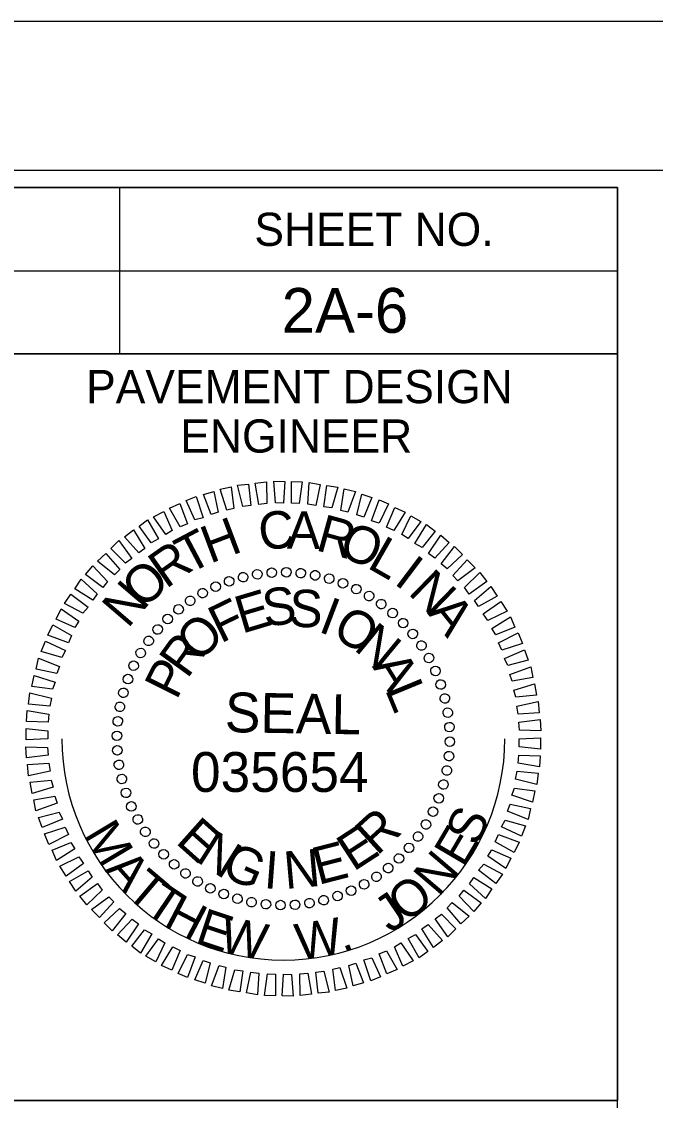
# Model space of a CAD drawing. Extents: x 957297 to 961629, y 830661 to 840840.
# Drawn here: x 960288 to 960383.5, y 834216.4 to 834378.9 of the extents above; entities that cross this region are included whole.
import ezdxf

# ---------------------------------------------------------------- set-up
doc = ezdxf.new("R2010")
doc.units = 0
for name, color, linetype in [('Scratch_Level_0', 7, 'Continuous'), ('Sheet Data Field CELL', 7, 'Continuous'), ('Sheet Plot Border Inside CELL', 7, 'Continuous'), ('Sheet Plot Border Outside CELL', 7, 'Continuous'), ('Sheet Professional Seal CELL', 7, 'Continuous'), ('Sheet Profile Grid Minor CELL', 7, 'Continuous'), ('Sheet Sticker Exception Certification CELL', 7, 'Continuous'), ('Sheet Typical CELL', 7, 'Continuous')]:
    doc.layers.add(name, color=color, linetype=linetype)

msp = doc.modelspace()

# ---------------------------------------------------------------- linework, layer by layer
at = {"layer": 'Scratch_Level_0'}
msp.add_arc((960327.47, 834270.85), 33.36, 180, 360, dxfattribs=at)
at = {"layer": 'Sheet Plot Border Inside CELL'}
msp.add_lwpolyline([(960390.3, 834356.46), (958723.8, 834356.46), (958723.8, 833301.36), (960390.3, 833301.36)], close=True, dxfattribs=at)
at = {"layer": 'Sheet Plot Border Outside CELL'}
msp.add_lwpolyline([(960394.8, 834378.91), (958710.8, 834378.91), (958710.8, 833278.91), (960394.8, 833278.91)], close=True, dxfattribs=at)
at = {"layer": 'Sheet Professional Seal CELL'}
for p, q in [((960323.57, 834295.6), (960323.57, 834295.6)), ((960325.72, 834295.9), (960325.72, 834295.9)), ((960327.92, 834295.95), (960327.92, 834295.95)), ((960330.12, 834295.8), (960330.12, 834295.8)), ((960319.27, 834294.6), (960319.27, 834294.6)), ((960321.37, 834295.2), (960321.37, 834295.2)), ((960332.27, 834295.45), (960332.27, 834295.45)), ((960334.37, 834295), (960334.37, 834295)), ((960336.47, 834294.3), (960336.47, 834294.3)), ((960315.32, 834292.8), (960315.32, 834292.8)), ((960317.27, 834293.8), (960317.27, 834293.8)), ((960338.47, 834293.4), (960338.47, 834293.4)), ((960340.42, 834292.4), (960340.42, 834292.4)), ((960313.42, 834291.65), (960313.42, 834291.65)), ((960342.22, 834291.15), (960342.22, 834291.15)), ((960311.67, 834290.4), (960311.67, 834290.4)), ((960343.97, 834289.8), (960343.97, 834289.8)), ((960310.02, 834288.9), (960310.02, 834288.9)), ((960345.52, 834288.3), (960345.52, 834288.3)), ((960308.52, 834287.35), (960308.52, 834287.35)), ((960347.02, 834286.65), (960347.02, 834286.65)), ((960307.17, 834285.6), (960307.17, 834285.6)), ((960348.27, 834284.9), (960348.27, 834284.9)), ((960305.92, 834283.8), (960305.92, 834283.8)), ((960349.42, 834283), (960349.42, 834283)), ((960304.92, 834281.85), (960304.92, 834281.85)), ((960350.42, 834281.05), (960350.42, 834281.05)), ((960304.02, 834279.85), (960304.02, 834279.85)), ((960303.32, 834277.75), (960303.32, 834277.75)), ((960351.22, 834279.05), (960351.22, 834279.05)), ((960351.82, 834276.95), (960351.82, 834276.95)), ((960302.87, 834275.65), (960302.87, 834275.65)), ((960352.22, 834274.75), (960352.22, 834274.75)), ((960302.52, 834273.5), (960302.52, 834273.5)), ((960302.37, 834271.3), (960302.37, 834271.3)), ((960352.52, 834272.6), (960352.52, 834272.6)), ((960327.47, 834270.85), (960327.47, 834270.85)), ((960352.57, 834270.4), (960352.57, 834270.4)), ((960302.42, 834269.1), (960302.42, 834269.1)), ((960352.42, 834268.2), (960352.42, 834268.2)), ((960302.72, 834266.95), (960302.72, 834266.95)), ((960303.12, 834264.75), (960303.12, 834264.75)), ((960352.07, 834266.05), (960352.07, 834266.05)), ((960351.62, 834263.95), (960351.62, 834263.95)), ((960303.72, 834262.65), (960303.72, 834262.65)), ((960350.92, 834261.85), (960350.92, 834261.85)), ((960304.52, 834260.65), (960304.52, 834260.65)), ((960350.02, 834259.85), (960350.02, 834259.85)), ((960305.52, 834258.7), (960305.52, 834258.7)), ((960306.67, 834256.8), (960306.67, 834256.8)), ((960349.02, 834257.9), (960349.02, 834257.9)), ((960307.92, 834255.05), (960307.92, 834255.05)), ((960347.77, 834256.1), (960347.77, 834256.1)), ((960309.42, 834253.4), (960309.42, 834253.4)), ((960346.42, 834254.35), (960346.42, 834254.35)), ((960310.97, 834251.9), (960310.97, 834251.9)), ((960344.92, 834252.8), (960344.92, 834252.8)), ((960312.72, 834250.55), (960312.72, 834250.55)), ((960343.27, 834251.3), (960343.27, 834251.3)), ((960314.52, 834249.3), (960314.52, 834249.3)), ((960339.62, 834248.9), (960339.62, 834248.9)), ((960341.52, 834250.05), (960341.52, 834250.05)), ((960316.47, 834248.3), (960316.47, 834248.3)), ((960318.47, 834247.4), (960318.47, 834247.4)), ((960335.67, 834247.1), (960335.67, 834247.1)), ((960337.67, 834247.9), (960337.67, 834247.9)), ((960320.57, 834246.7), (960320.57, 834246.7)), ((960322.67, 834246.25), (960322.67, 834246.25)), ((960324.82, 834245.9), (960324.82, 834245.9)), ((960327.02, 834245.75), (960327.02, 834245.75)), ((960329.22, 834245.8), (960329.22, 834245.8)), ((960331.37, 834246.1), (960331.37, 834246.1)), ((960333.57, 834246.5), (960333.57, 834246.5))]:
    msp.add_line(p, q, dxfattribs=at)
for points in [[(960318.97, 834305.3), (960317.92, 834308.45), (960319.62, 834308.8), (960320.02, 834305.55)], [(960321.37, 834305.85), (960320.57, 834309.05), (960322.22, 834309.2), (960322.57, 834306)], [(960323.77, 834306.15), (960323.22, 834309.35), (960324.92, 834309.55), (960324.97, 834306.3)], [(960326.27, 834306.4), (960326.02, 834309.65), (960327.67, 834309.6), (960327.47, 834306.35)], [(960328.67, 834306.35), (960328.67, 834309.6), (960330.32, 834309.55), (960329.87, 834306.3)], [(960331.17, 834306.2), (960331.37, 834309.45), (960333.02, 834309.15), (960332.37, 834306)], [(960333.57, 834305.8), (960334.02, 834309), (960335.67, 834308.75), (960334.77, 834305.65)], [(960314.12, 834303.85), (960312.82, 834306.75), (960314.32, 834307.35), (960315.37, 834304.15)], [(960316.57, 834304.65), (960315.42, 834307.65), (960316.97, 834308.1), (960317.62, 834305)], [(960336.12, 834305.25), (960336.62, 834308.5), (960338.32, 834308.1), (960337.17, 834305)], [(960338.52, 834304.6), (960339.27, 834307.7), (960340.82, 834307.2), (960339.57, 834304.25)], [(960311.92, 834302.8), (960310.32, 834305.6), (960311.87, 834306.3), (960313.02, 834303.25)], [(960340.77, 834303.7), (960341.92, 834306.85), (960343.32, 834306.25), (960341.92, 834303.35)], [(960343.02, 834302.75), (960344.27, 834305.7), (960345.82, 834305), (960344.12, 834302.2)], [(960307.57, 834300.35), (960305.72, 834302.9), (960307.02, 834303.85), (960308.67, 834300.95)], [(960309.77, 834301.6), (960307.92, 834304.3), (960309.47, 834305.1), (960310.72, 834302.2)], [(960345.32, 834301.6), (960346.67, 834304.45), (960348.17, 834303.6), (960346.27, 834301)], [(960305.67, 834298.85), (960303.52, 834301.25), (960304.87, 834302.3), (960306.62, 834299.5)], [(960347.27, 834300.25), (960349.02, 834303.15), (960350.32, 834302.1), (960348.37, 834299.65)], [(960303.67, 834297.3), (960301.47, 834299.5), (960302.67, 834300.7), (960304.62, 834298)], [(960349.32, 834298.75), (960351.17, 834301.5), (960352.47, 834300.4), (960350.27, 834298.05)], [(960351.22, 834297.2), (960353.27, 834299.8), (960354.47, 834298.6), (960352.17, 834296.45)], [(960302.02, 834295.55), (960299.47, 834297.6), (960300.72, 834298.75), (960302.82, 834296.35)], [(960353.02, 834295.45), (960355.17, 834297.8), (960356.37, 834296.6), (960353.77, 834294.65)], [(960300.27, 834293.65), (960297.67, 834295.6), (960298.77, 834296.9), (960300.97, 834294.55)], [(960354.77, 834293.65), (960357.07, 834295.9), (960358.12, 834294.55), (960355.47, 834292.65)], [(960298.77, 834291.75), (960296.07, 834293.45), (960297.02, 834294.9), (960299.42, 834292.7)], [(960297.27, 834289.75), (960294.47, 834291.25), (960295.47, 834292.65), (960298.07, 834290.65)], [(960356.27, 834291.7), (960358.72, 834293.8), (960359.67, 834292.35), (960356.87, 834290.75)], [(960357.57, 834289.65), (960360.22, 834291.55), (960361.17, 834290.05), (960358.27, 834288.65)], [(960296.07, 834287.6), (960293.22, 834288.85), (960293.97, 834290.4), (960296.67, 834288.55)], [(960358.87, 834287.45), (960361.67, 834289.2), (960362.32, 834287.65), (960359.47, 834286.5)], [(960295.07, 834285.3), (960291.97, 834286.45), (960292.72, 834288), (960295.57, 834286.4)], [(960359.87, 834285.3), (960362.82, 834286.8), (960363.47, 834285.2), (960360.37, 834284.2)], [(960294.07, 834283.1), (960290.97, 834284), (960291.62, 834285.55), (960294.62, 834284.15)], [(960360.77, 834282.95), (960363.82, 834284.25), (960364.37, 834282.7), (960361.27, 834281.9)], [(960293.32, 834280.7), (960290.22, 834281.35), (960290.57, 834283), (960293.72, 834281.75)], [(960361.57, 834280.55), (960364.77, 834281.7), (960365.07, 834280.05), (960361.92, 834279.5)], [(960292.67, 834278.3), (960289.57, 834278.7), (960289.92, 834280.4), (960293.07, 834279.35)], [(960292.27, 834275.75), (960289.07, 834276.05), (960289.27, 834277.75), (960292.52, 834276.95)], [(960362.17, 834278.15), (960365.32, 834279.1), (960365.62, 834277.4), (960362.47, 834277.1)], [(960362.62, 834275.75), (960365.87, 834276.45), (960366.02, 834274.75), (960362.82, 834274.55)], [(960292.02, 834273.35), (960288.77, 834273.45), (960288.87, 834275.1), (960292.12, 834274.55)], [(960362.92, 834273.35), (960366.17, 834273.75), (960366.27, 834272.05), (960363.02, 834272.15)], [(960291.97, 834270.85), (960288.72, 834270.7), (960288.72, 834272.4), (960291.97, 834272.05)], [(960292.02, 834268.35), (960288.77, 834267.95), (960288.67, 834269.65), (960291.92, 834269.55)], [(960362.97, 834270.85), (960366.22, 834271), (960366.22, 834269.3), (960362.97, 834269.65)], [(960362.92, 834268.35), (960366.17, 834268.25), (960366.07, 834266.6), (960362.82, 834267.15)], [(960292.32, 834265.95), (960289.07, 834265.25), (960288.92, 834266.95), (960292.12, 834267.15)], [(960362.67, 834265.95), (960365.87, 834265.65), (960365.67, 834263.95), (960362.42, 834264.75)], [(960292.77, 834263.55), (960289.62, 834262.6), (960289.32, 834264.3), (960292.47, 834264.6)], [(960362.27, 834263.4), (960365.37, 834263), (960365.02, 834261.3), (960361.87, 834262.35)], [(960293.37, 834261.15), (960290.17, 834260), (960289.87, 834261.65), (960293.02, 834262.2)], [(960361.62, 834261), (960364.72, 834260.35), (960364.37, 834258.7), (960361.22, 834259.95)], [(960294.17, 834258.75), (960291.12, 834257.45), (960290.57, 834259), (960293.67, 834259.8)], [(960360.87, 834258.6), (960363.97, 834257.7), (960363.32, 834256.15), (960360.32, 834257.55)], [(960295.07, 834256.4), (960292.12, 834254.9), (960291.47, 834256.5), (960294.57, 834257.5)], [(960296.07, 834254.25), (960293.27, 834252.5), (960292.62, 834254.05), (960295.47, 834255.2)], [(960359.87, 834256.4), (960362.97, 834255.25), (960362.22, 834253.7), (960359.37, 834255.3)], [(960358.87, 834254.1), (960361.72, 834252.85), (960360.97, 834251.3), (960358.27, 834253.15)], [(960297.37, 834252.05), (960294.72, 834250.15), (960293.77, 834251.65), (960296.67, 834253.05)], [(960357.67, 834251.95), (960360.47, 834250.45), (960359.47, 834249.05), (960356.87, 834251.05)], [(960298.67, 834250), (960296.22, 834247.9), (960295.27, 834249.35), (960298.07, 834250.95)], [(960300.17, 834248.05), (960297.87, 834245.8), (960296.82, 834247.15), (960299.47, 834249.05)], [(960356.17, 834249.95), (960358.87, 834248.25), (960357.92, 834246.8), (960355.52, 834249)], [(960301.92, 834246.25), (960299.77, 834243.9), (960298.57, 834245.1), (960301.17, 834247.05)], [(960354.67, 834248.05), (960357.27, 834246.1), (960356.17, 834244.8), (960353.97, 834247.15)], [(960303.72, 834244.5), (960301.67, 834241.9), (960300.47, 834243.1), (960302.77, 834245.25)], [(960352.92, 834246.15), (960355.47, 834244.1), (960354.22, 834242.95), (960352.12, 834245.35)], [(960305.62, 834242.95), (960303.77, 834240.2), (960302.47, 834241.3), (960304.67, 834243.65)], [(960351.27, 834244.4), (960353.47, 834242.2), (960352.27, 834241), (960350.32, 834243.7)], [(960307.67, 834241.45), (960305.92, 834238.55), (960304.62, 834239.6), (960306.57, 834242.05)], [(960349.27, 834242.85), (960351.42, 834240.45), (960350.07, 834239.4), (960348.32, 834242.2)], [(960309.62, 834240.1), (960308.27, 834237.25), (960306.77, 834238.1), (960308.67, 834240.7)], [(960347.37, 834241.35), (960349.22, 834238.8), (960347.92, 834237.85), (960346.27, 834240.75)], [(960311.92, 834238.95), (960310.67, 834236), (960309.12, 834236.7), (960310.82, 834239.5)], [(960343.02, 834238.9), (960344.62, 834236.1), (960343.07, 834235.4), (960341.92, 834238.45)], [(960345.17, 834240.1), (960347.02, 834237.4), (960345.47, 834236.6), (960344.22, 834239.5)], [(960314.17, 834238), (960313.02, 834234.85), (960311.62, 834235.45), (960313.02, 834238.35)], [(960316.42, 834237.1), (960315.67, 834234), (960314.12, 834234.5), (960315.37, 834237.45)], [(960338.37, 834237.05), (960339.52, 834234.05), (960337.97, 834233.6), (960337.32, 834236.7)], [(960340.82, 834237.85), (960342.12, 834234.95), (960340.62, 834234.35), (960339.57, 834237.55)], [(960318.82, 834236.45), (960318.32, 834233.2), (960316.62, 834233.6), (960317.77, 834236.7)], [(960321.37, 834235.9), (960320.92, 834232.7), (960319.27, 834232.95), (960320.17, 834236.05)], [(960323.77, 834235.5), (960323.57, 834232.25), (960321.92, 834232.55), (960322.57, 834235.7)], [(960331.17, 834235.55), (960331.72, 834232.35), (960330.02, 834232.15), (960329.97, 834235.4)], [(960333.57, 834235.85), (960334.37, 834232.65), (960332.72, 834232.5), (960332.37, 834235.7)], [(960335.97, 834236.4), (960337.02, 834233.25), (960335.32, 834232.9), (960334.92, 834236.15)], [(960326.27, 834235.35), (960326.27, 834232.1), (960324.62, 834232.15), (960325.07, 834235.4)], [(960328.67, 834235.3), (960328.92, 834232.05), (960327.27, 834232.1), (960327.47, 834235.35)]]:
    msp.add_lwpolyline(points, close=True, dxfattribs=at)
for centre, major_axis in [((960321.4, 834295.19), (-0.174, 0.699)), ((960323.54, 834295.62), (-0.113, 0.711)), ((960325.72, 834295.87), (-0.05, 0.718)), ((960327.9, 834295.93), (0.013, 0.72)), ((960330.09, 834295.79), (0.075, 0.716)), ((960332.25, 834295.47), (0.137, 0.707)), ((960334.38, 834294.96), (0.198, 0.692)), ((960317.27, 834293.76), (-0.293, 0.658)), ((960319.3, 834294.57), (-0.234, 0.681)), ((960336.45, 834294.27), (0.258, 0.672)), ((960338.46, 834293.39), (0.316, 0.647)), ((960313.44, 834291.64), (-0.403, 0.597)), ((960315.31, 834292.79), (-0.349, 0.63)), ((960340.38, 834292.35), (0.371, 0.617)), ((960311.68, 834290.34), (-0.453, 0.56)), ((960342.21, 834291.14), (0.423, 0.582)), ((960310.04, 834288.89), (-0.5, 0.518)), ((960343.92, 834289.78), (0.472, 0.543)), ((960345.51, 834288.27), (0.518, 0.5)), ((960308.54, 834287.31), (-0.543, 0.472)), ((960346.96, 834286.64), (0.56, 0.453)), ((960307.18, 834285.59), (-0.582, 0.423)), ((960305.97, 834283.77), (-0.617, 0.371)), ((960348.26, 834284.88), (0.597, 0.403)), ((960304.92, 834281.85), (-0.647, 0.316)), ((960349.4, 834283.01), (0.63, 0.349)), ((960350.38, 834281.05), (0.658, 0.293)), ((960304.05, 834279.84), (-0.672, 0.258)), ((960351.18, 834279.02), (0.681, 0.234)), ((960303.36, 834277.77), (-0.692, 0.198)), ((960351.8, 834276.92), (0.699, 0.174)), ((960302.85, 834275.64), (-0.707, 0.137)), ((960352.24, 834274.78), (0.711, 0.113)), ((960302.52, 834273.47), (-0.716, 0.075)), ((960352.49, 834272.6), (0.718, 0.05)), ((960302.39, 834271.29), (-0.72, 0.013)), ((960302.45, 834269.1), (-0.718, -0.05)), ((960352.54, 834270.41), (0.72, -0.013)), ((960352.41, 834268.23), (0.716, -0.075)), ((960302.69, 834266.93), (-0.711, -0.113)), ((960352.09, 834266.07), (0.707, -0.137)), ((960303.13, 834264.78), (-0.699, -0.174)), ((960351.57, 834263.94), (0.692, -0.198)), ((960303.75, 834262.69), (-0.681, -0.234)), ((960304.55, 834260.65), (-0.658, -0.293)), ((960350.88, 834261.86), (0.672, -0.258)), ((960350.01, 834259.86), (0.647, -0.316)), ((960305.53, 834258.69), (-0.63, -0.349)), ((960348.96, 834257.93), (0.617, -0.371)), ((960306.67, 834256.83), (-0.597, -0.403)), ((960347.76, 834256.11), (0.582, -0.423)), ((960307.98, 834255.07), (-0.56, -0.453)), ((960346.39, 834254.4), (0.543, -0.472)), ((960309.43, 834253.43), (-0.518, -0.5)), ((960344.89, 834252.81), (0.5, -0.518)), ((960311.01, 834251.92), (-0.472, -0.543)), ((960343.25, 834251.36), (0.453, -0.56)), ((960312.72, 834250.56), (-0.423, -0.582)), ((960314.55, 834249.35), (-0.371, -0.617)), ((960341.49, 834250.06), (0.403, -0.597)), ((960316.47, 834248.31), (-0.316, -0.647)), ((960337.67, 834247.94), (0.293, -0.658)), ((960339.63, 834248.92), (0.349, -0.63)), ((960318.48, 834247.44), (-0.258, -0.672)), ((960320.55, 834246.74), (-0.198, -0.692)), ((960322.68, 834246.23), (-0.137, -0.707)), ((960331.39, 834246.08), (0.113, -0.711)), ((960333.53, 834246.52), (0.174, -0.699)), ((960335.63, 834247.14), (0.234, -0.681)), ((960324.84, 834245.91), (-0.075, -0.716)), ((960327.03, 834245.78), (-0.013, -0.72)), ((960329.22, 834245.83), (0.05, -0.718))]:
    msp.add_ellipse(centre, major_axis=major_axis, ratio=0.999708, dxfattribs=at)
at = {"layer": 'Sheet Sticker Exception Certification CELL'}
msp.add_line((960177.75, 834216.36), (960377.79, 834216.36), dxfattribs=at)
at = {"layer": 'Sheet Typical CELL'}
for p, q in [((960302.8, 834353.86), (960302.8, 834328.86)), ((960177.75, 834341.36), (960377.8, 834341.36))]:
    msp.add_line(p, q, dxfattribs=at)
for points in [[(960377.8, 834353.91), (958877.8, 834353.91), (958877.8, 833303.91), (960377.8, 833303.91)], [(960177.75, 834353.91), (960377.8, 834353.91), (960377.8, 834328.86), (960177.75, 834328.86)], [(960277.8, 834328.86), (960377.8, 834328.86), (960377.8, 834216.36), (960277.8, 834216.36)]]:
    msp.add_lwpolyline(points, close=True, dxfattribs=at)

# ---------------------------------------------------------------- texts
at = {"layer": 'Sheet Data Field CELL'}
msp.add_text('2A-6', height=6.75, dxfattribs=at).set_placement((960327.21, 834332.01))
at = {"layer": 'Sheet Professional Seal CELL'}
for s, height, rotation, p in [('H', 5.64, 20.6195, (960316.42, 834297.2)), ('C', 5.64, 6.2199, (960324.02, 834299.2)), ('A', 5.64, 359.0203, (960327.97, 834299.5)), ('R', 5.64, 344.6211, (960332.17, 834299.3)), ('T', 5.64, 27.8198, (960313.17, 834295.55)), ('O', 5.64, 337.4212, (960335.52, 834298.55)), ('L', 5.64, 330.2209, (960339.92, 834296.7)), ('R', 5.64, 35.0205, (960309.77, 834293.35)), ('O', 5.64, 42.2217, (960306.32, 834290.25)), ('I', 5.64, 323.0201, (960343.97, 834294.3)), ('N', 5.64, 315.8189, (960346.12, 834292.75)), ('N', 5.64, 49.4235, (960304.02, 834287.35)), ('E', 5.64, 16.6111, (960321.22, 834286.65)), ('S', 5.64, 7.2556, (960324.67, 834287.7)), ('S', 5.64, 357.9004, (960328.27, 834287.75)), ('F', 5.64, 25.967, (960318.02, 834285.15)), ('I', 5.64, 339.1896, (960332.57, 834287.05)), ('A', 5.64, 308.6172, (960349.07, 834289.8)), ('O', 5.64, 44.6812, (960314.72, 834282.2)), ('O', 5.64, 329.8335, (960334.57, 834286.35)), ('N', 5.64, 320.4766, (960337.92, 834284.35)), ('R', 5.64, 54.0397, (960312.97, 834279.75)), ('P', 5.64, 63.3989, (960311.37, 834276.55)), ('A', 5.64, 301.7603, (960340.77, 834281.75)), ('L', 5.64, 292.4008, (960342.72, 834278.3)), ('SEAL', 5.998, 359, (960318.62, 834271.85)), ('R', 5.64, 42.4814, (960341.57, 834253.1)), ('E', 5.64, 318.2769, (960311.07, 834255.2)), ('N', 5.64, 327.634, (960314.07, 834252.5)), ('E', 5.64, 33.1241, (960338.02, 834250.75)), ('E', 5.64, 14.4118, (960332.72, 834248.8)), ('G', 5.64, 336.9902, (960317.87, 834250.25)), ('I', 5.64, 355.7012, (960324.42, 834248.35)), ('N', 5.64, 5.0564, (960327.77, 834248.2))]:
    msp.add_text(s, height=height, rotation=rotation, dxfattribs=at).set_placement(p)
at = {"layer": 'Sheet Profile Grid Minor CELL'}
msp.add_text('035654', height=5.998, dxfattribs=at).set_placement((960313.55, 834262.84))
for s, rotation, p in [('S', 66.1201, (960356.72, 834254.5)), ('M', 300.9117, (960297.24, 834256.38)), ('E', 59.5371, (960354.65, 834251.26)), ('N', 49.6054, (960350.86, 834246.86)), ('A', 311.5876, (960300.45, 834251.03)), ('T', 319.7734, (960303.55, 834247.39)), ('T', 326.0702, (960306.26, 834244.9)), ('O', 38.9008, (960346, 834242.94)), ('H', 332.3669, (960309.24, 834242.74)), ('J', 34.0323, (960343.56, 834241.46)), ('E', 341.6117, (960313.99, 834240.17)), ('W', 348.1947, (960317.6, 834238.83)), ('W', 9.2459, (960329.76, 834237.42)), ('.', 20.852, (960336.44, 834238.57))]:
    msp.add_text(s, height=5.5, rotation=rotation, dxfattribs=at).set_placement(p)
at = {"layer": 'Sheet Typical CELL'}
for s, height, p in [('SHEET NO.', 5, (960323.1, 834345.11)), ('PAVEMENT DESIGN', 5.0001, (960297.75, 834321.41)), ('ENGINEER', 5, (960311.95, 834313.96))]:
    msp.add_text(s, height=height, dxfattribs=at).set_placement(p)

doc.saveas('drawing.dxf')
